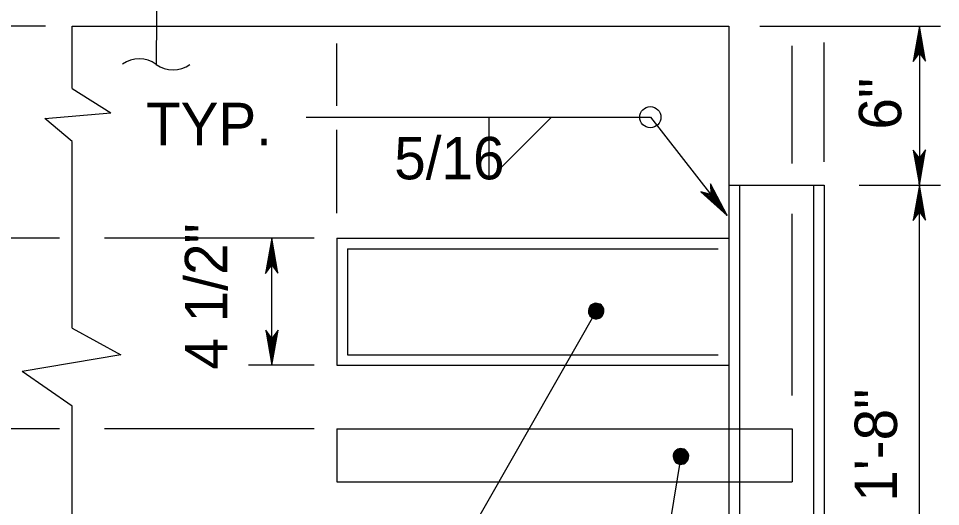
# Model space of a CAD drawing. Extents: x 499883 to 500983, y 499104 to 499764.
# Drawn here: x 500293.1 to 500380.1, y 499651.5 to 499697.5 of the extents above; entities that cross this region are included whole.
import ezdxf

# ---------------------------------------------------------------- set-up
doc = ezdxf.new("R2010")
doc.units = 0
doc.layers.add('24', color=7, linetype='Continuous')
doc.layers.add('5', color=7, linetype='Continuous')

msp = doc.modelspace()

# ---------------------------------------------------------------- linework, layer by layer
at = {"layer": '24'}
for points in [[(500347.639, 499669.947), (500304.956, 499595.144), (500297.036, 499595.144)], [(500355.634, 499656.248), (500348.094, 499610.467), (500342.218, 499610.467)]]:
    msp.add_lwpolyline(points, dxfattribs=at)
for centre, radius, start, end in [((500304.512, 499690.964), 2.768, 54.46959, 124.83479), ((500307.729, 499695.47), 2.768, 234.46959, 304.83479), ((500347.638, 499669.947), 0.738, 60.29128, 240.29128), ((500347.638, 499669.947), 0.714, 60.29128, 240.29128), ((500347.638, 499669.947), 0.689, 60.29128, 240.29128), ((500347.638, 499669.947), 0.664, 60.29128, 240.29128), ((500347.638, 499669.947), 0.64, 60.29128, 240.29128), ((500347.638, 499669.947), 0.615, 60.29128, 240.29128), ((500347.638, 499669.947), 0.591, 60.29128, 240.29128), ((500347.638, 499669.947), 0.566, 60.29128, 240.29128), ((500347.638, 499669.947), 0.541, 60.29128, 240.29128), ((500347.638, 499669.947), 0.517, 60.29128, 240.29128), ((500347.638, 499669.947), 0.492, 60.29128, 240.29128), ((500347.638, 499669.947), 0.468, 60.29128, 240.29128), ((500347.638, 499669.947), 0.443, 60.29128, 240.29128), ((500347.638, 499669.947), 0.418, 60.29128, 240.29128), ((500347.638, 499669.947), 0.394, 60.29128, 240.29128), ((500347.638, 499669.947), 0.369, 60.29128, 240.29128), ((500347.638, 499669.947), 0.738, 240.29128, 60.29128), ((500347.638, 499669.947), 0.714, 240.29128, 60.29128), ((500347.638, 499669.947), 0.344, 60.29128, 240.29128), ((500347.638, 499669.947), 0.689, 240.29128, 60.29128), ((500347.638, 499669.947), 0.664, 240.29128, 60.29128), ((500347.638, 499669.947), 0.32, 60.29128, 240.29128), ((500347.638, 499669.947), 0.64, 240.29128, 60.29128), ((500347.638, 499669.947), 0.615, 240.29128, 60.29128), ((500347.638, 499669.947), 0.295, 60.29128, 240.29128), ((500347.638, 499669.947), 0.591, 240.29128, 60.29128), ((500347.638, 499669.947), 0.566, 240.29128, 60.29128), ((500347.638, 499669.947), 0.541, 240.29128, 60.29128), ((500347.638, 499669.947), 0.517, 240.29128, 60.29128), ((500347.638, 499669.947), 0.492, 240.29128, 60.29128), ((500347.638, 499669.947), 0.468, 240.29128, 60.29128), ((500347.638, 499669.947), 0.443, 240.29128, 60.29128), ((500347.638, 499669.947), 0.418, 240.29128, 60.29128), ((500347.638, 499669.947), 0.394, 240.29128, 60.29128), ((500347.638, 499669.947), 0.369, 240.29128, 60.29128), ((500347.638, 499669.947), 0.344, 240.29128, 60.29128), ((500347.638, 499669.947), 0.271, 60.29128, 240.29128), ((500347.638, 499669.947), 0.246, 60.29128, 240.29128), ((500347.638, 499669.947), 0.221, 60.29128, 240.29128), ((500347.638, 499669.947), 0.197, 60.29128, 240.29128), ((500347.638, 499669.947), 0.172, 60.29128, 240.29128), ((500347.638, 499669.947), 0.32, 240.29128, 60.29128), ((500347.638, 499669.947), 0.148, 60.29128, 240.29128), ((500347.638, 499669.947), 0.295, 240.29128, 60.29128), ((500347.638, 499669.947), 0.271, 240.29128, 60.29128), ((500347.638, 499669.947), 0.123, 60.29128, 240.29128), ((500347.638, 499669.947), 0.246, 240.29128, 60.29128), ((500347.638, 499669.947), 0.221, 240.29128, 60.29128), ((500347.638, 499669.947), 0.0984, 60.29128, 240.29128), ((500347.638, 499669.947), 0.197, 240.29128, 60.29128), ((500347.638, 499669.947), 0.172, 240.29128, 60.29128), ((500347.638, 499669.947), 0.148, 240.29128, 60.29128), ((500347.638, 499669.947), 0.0738, 60.29128, 240.29128), ((500347.638, 499669.947), 0.123, 240.29128, 60.29128), ((500347.638, 499669.947), 0.0492, 60.29128, 240.29128), ((500347.638, 499669.947), 0.0984, 240.29128, 60.29128), ((500347.638, 499669.947), 0.0738, 240.29128, 60.29128), ((500347.638, 499669.947), 0.0492, 240.29128, 60.29128), ((500347.638, 499669.947), 0.0246, 60.29128, 240.29128), ((500347.638, 499669.947), 0.0246, 240.29128, 60.29128), ((500355.634, 499656.247), 0.738, 80.64766, 260.64766), ((500355.634, 499656.247), 0.714, 80.64766, 260.64766), ((500355.634, 499656.247), 0.689, 80.64766, 260.64766), ((500355.634, 499656.247), 0.664, 80.64766, 260.64766), ((500355.634, 499656.247), 0.64, 80.64766, 260.64766), ((500355.634, 499656.247), 0.615, 80.64766, 260.64766), ((500355.634, 499656.247), 0.591, 80.64766, 260.64766), ((500355.634, 499656.247), 0.566, 80.64766, 260.64766), ((500355.634, 499656.247), 0.541, 80.64766, 260.64766), ((500355.634, 499656.247), 0.517, 80.64766, 260.64766), ((500355.634, 499656.247), 0.492, 80.64766, 260.64766), ((500355.634, 499656.247), 0.468, 80.64766, 260.64766), ((500355.634, 499656.247), 0.443, 80.64766, 260.64766), ((500355.634, 499656.247), 0.418, 80.64766, 260.64766), ((500355.634, 499656.247), 0.394, 80.64766, 260.64766), ((500355.634, 499656.247), 0.369, 80.64766, 260.64766), ((500355.634, 499656.247), 0.344, 80.64766, 260.64766), ((500355.634, 499656.247), 0.32, 80.64766, 260.64766), ((500355.634, 499656.247), 0.295, 80.64766, 260.64766), ((500355.634, 499656.247), 0.271, 80.64766, 260.64766), ((500355.634, 499656.247), 0.246, 80.64766, 260.64766), ((500355.634, 499656.247), 0.221, 80.64766, 260.64766), ((500355.634, 499656.247), 0.197, 80.64766, 260.64766), ((500355.634, 499656.247), 0.172, 80.64766, 260.64766), ((500355.634, 499656.247), 0.148, 80.64766, 260.64766), ((500355.634, 499656.247), 0.123, 80.64766, 260.64766), ((500355.634, 499656.247), 0.738, 260.64766, 80.64766), ((500355.634, 499656.247), 0.714, 260.64766, 80.64766), ((500355.634, 499656.247), 0.689, 260.64766, 80.64766), ((500355.634, 499656.247), 0.664, 260.64766, 80.64766), ((500355.634, 499656.247), 0.64, 260.64766, 80.64766), ((500355.634, 499656.247), 0.615, 260.64766, 80.64766), ((500355.634, 499656.247), 0.0984, 80.64766, 260.64766), ((500355.634, 499656.247), 0.591, 260.64766, 80.64766), ((500355.634, 499656.247), 0.566, 260.64766, 80.64766), ((500355.634, 499656.247), 0.541, 260.64766, 80.64766), ((500355.634, 499656.247), 0.517, 260.64766, 80.64766), ((500355.634, 499656.247), 0.492, 260.64766, 80.64766), ((500355.634, 499656.247), 0.468, 260.64766, 80.64766), ((500355.634, 499656.247), 0.0738, 80.64766, 260.64766), ((500355.634, 499656.247), 0.443, 260.64766, 80.64766), ((500355.634, 499656.247), 0.418, 260.64766, 80.64766), ((500355.634, 499656.247), 0.394, 260.64766, 80.64766), ((500355.634, 499656.247), 0.369, 260.64766, 80.64766), ((500355.634, 499656.247), 0.344, 260.64766, 80.64766), ((500355.634, 499656.247), 0.32, 260.64766, 80.64766), ((500355.634, 499656.247), 0.295, 260.64766, 80.64766), ((500355.634, 499656.247), 0.271, 260.64766, 80.64766), ((500355.634, 499656.247), 0.246, 260.64766, 80.64766), ((500355.634, 499656.247), 0.221, 260.64766, 80.64766), ((500355.634, 499656.247), 0.197, 260.64766, 80.64766), ((500355.634, 499656.247), 0.172, 260.64766, 80.64766), ((500355.634, 499656.247), 0.148, 260.64766, 80.64766), ((500355.634, 499656.247), 0.123, 260.64766, 80.64766), ((500355.634, 499656.247), 0.0984, 260.64766, 80.64766), ((500355.634, 499656.247), 0.0738, 260.64766, 80.64766), ((500355.634, 499656.247), 0.0492, 80.64766, 260.64766), ((500355.634, 499656.247), 0.0246, 80.64766, 260.64766), ((500355.634, 499656.247), 0.0492, 260.64766, 80.64766), ((500355.634, 499656.247), 0.0246, 260.64766, 80.64766)]:
    msp.add_arc(centre, radius, start, end, dxfattribs=at)
at = {"layer": '5'}
for p, q in [((500295.678, 499696.814), (500284.277, 499696.814)), ((500298.192, 499696.814), (500360.145, 499696.814)), ((500298.192, 499690.928), (500298.192, 499696.814)), ((500360.145, 499696.814), (500360.145, 499681.826)), ((500363.071, 499696.814), (500380.13, 499696.814)), ((500378.131, 499696.814), (500378.131, 499681.826)), ((500323.174, 499689.306), (500323.174, 499695.177)), ((500366.141, 499683.862), (500366.141, 499694.949)), ((500369.139, 499684.02), (500369.139, 499695.265)), ((500298.192, 499690.928), (500301.847, 499688.646)), ((500295.625, 499688.117), (500301.847, 499688.646)), ((500298.192, 499685.939), (500295.625, 499688.117)), ((500320.265, 499688.235), (500352.747, 499688.235)), ((500343.42, 499688.235), (500337.529, 499682.344)), ((500337.529, 499682.344), (500337.529, 499688.235)), ((500352.747, 499688.235), (500360.005, 499678.955)), ((500323.174, 499679.192), (500323.174, 499687.045)), ((500298.192, 499668.328), (500298.192, 499685.939)), ((500360.145, 499681.826), (500369.139, 499681.826)), ((500360.145, 499681.826), (500360.145, 499630.865)), ((500361.144, 499681.826), (500361.144, 499630.865)), ((500368.139, 499681.826), (500368.139, 499630.865)), ((500369.139, 499681.826), (500369.139, 499616.875)), ((500372.436, 499681.826), (500380.13, 499681.826)), ((500378.131, 499630.865), (500378.131, 499681.826)), ((500366.141, 499662.004), (500366.141, 499679.11)), ((500296.993, 499676.83), (500284.277, 499676.83)), ((500321.027, 499676.83), (500301.229, 499676.83)), ((500317.03, 499664.839), (500317.03, 499676.83)), ((500323.174, 499676.83), (500360.145, 499676.83)), ((500323.174, 499676.83), (500323.174, 499664.839)), ((500324.173, 499675.831), (500359.146, 499675.831)), ((500324.173, 499675.831), (500324.173, 499665.838)), ((500298.192, 499668.328), (500302.773, 499665.813)), ((500302.773, 499665.813), (500293.463, 499664.268)), ((500324.173, 499665.838), (500359.146, 499665.838)), ((500298.192, 499660.998), (500293.463, 499664.268)), ((500321.027, 499664.839), (500314.819, 499664.839)), ((500323.174, 499664.839), (500360.145, 499664.839)), ((500298.192, 499636.713), (500298.192, 499660.998)), ((500296.993, 499658.843), (500284.277, 499658.843)), ((500321.027, 499658.843), (500301.229, 499658.843)), ((500323.174, 499658.843), (500366.141, 499658.843)), ((500323.174, 499658.843), (500323.174, 499653.847)), ((500366.141, 499658.843), (500366.141, 499653.847)), ((500323.174, 499653.847), (500366.141, 499653.847))]:
    msp.add_line(p, q, dxfattribs=at)
for points in [[(500301.41, 499711.376), (500306.231, 499711.376), (500306.121, 499693.217)], [(500378.131, 499696.814), (500377.544, 499693.491), (500378.131, 499694.284), (500378.71, 499693.508), (500378.131, 499696.814), (500378.138, 499696.593), (500377.588, 499693.584), (500378.139, 499694.347), (500378.664, 499693.642), (500378.148, 499696.475), (500378.131, 499696.364), (500377.674, 499693.785), (500378.139, 499694.364), (500378.59, 499693.769), (500378.131, 499696.313), (500378.148, 499696.203), (500377.741, 499693.949), (500378.131, 499694.387), (500378.537, 499693.94), (500378.148, 499695.882), (500378.148, 499695.694), (500377.825, 499694.116), (500378.122, 499694.423), (500378.453, 499694.093), (500378.131, 499695.661), (500378.121, 499695.483), (500377.918, 499694.297), (500378.149, 499694.525), (500378.376, 499694.278), (500378.131, 499695.32), (500378.115, 499695.153), (500377.979, 499694.44), (500378.139, 499694.558), (500378.316, 499694.363), (500378.131, 499695.066), (500378.021, 499694.601), (500378.148, 499694.668), (500378.275, 499694.464), (500378.149, 499694.949), (500378.072, 499694.644), (500378.173, 499694.772), (500378.233, 499694.625), (500378.139, 499694.771), (500378.122, 499694.695)], [(500378.131, 499681.826), (500378.719, 499685.15), (500378.131, 499684.356), (500377.553, 499685.132), (500378.131, 499681.826), (500378.125, 499682.047), (500378.676, 499685.057), (500378.124, 499684.293), (500377.599, 499684.998), (500378.115, 499682.166), (500378.131, 499682.276), (500378.59, 499684.855), (500378.125, 499684.276), (500377.674, 499684.872), (500378.132, 499682.327), (500378.115, 499682.438), (500378.522, 499684.691), (500378.132, 499684.253), (500377.726, 499684.701), (500378.115, 499682.758), (500378.115, 499682.946), (500378.438, 499684.524), (500378.141, 499684.217), (500377.81, 499684.548), (500378.131, 499682.979), (500378.141, 499683.157), (500378.345, 499684.344), (500378.115, 499684.116), (500377.887, 499684.363), (500378.131, 499683.32), (500378.148, 499683.488), (500378.285, 499684.2), (500378.124, 499684.083), (500377.947, 499684.277), (500378.132, 499683.574), (500378.242, 499684.039), (500378.115, 499683.972), (500377.988, 499684.176), (500378.115, 499683.691), (500378.191, 499683.996), (500378.09, 499683.869), (500378.031, 499684.015), (500378.124, 499683.869), (500378.141, 499683.946)], [(500360.005, 499678.955), (500358.42, 499681.935), (500358.446, 499680.947), (500357.513, 499681.203), (500360.005, 499678.955), (500359.864, 499679.125), (500358.443, 499681.834), (500358.479, 499680.894), (500357.631, 499681.125), (500359.783, 499679.212), (500359.727, 499679.309), (500358.5, 499681.623), (500358.49, 499680.88), (500357.768, 499681.071), (500359.696, 499679.349), (500359.615, 499679.426), (500358.547, 499681.452), (500358.51, 499680.866), (500357.915, 499680.969), (500359.417, 499679.679), (500359.302, 499679.827), (500358.584, 499681.269), (500358.539, 499680.844), (500358.075, 499680.9), (500359.294, 499679.863), (500359.193, 499680.009), (500358.622, 499681.069), (500358.581, 499680.748), (500358.249, 499680.802), (500359.084, 499680.131), (500358.995, 499680.274), (500358.663, 499680.919), (500358.609, 499680.728), (500358.349, 499680.771), (500358.928, 499680.332), (500358.729, 499680.766), (500358.67, 499680.635), (500358.444, 499680.717), (500358.842, 499680.413), (500358.715, 499680.701), (500358.714, 499680.538), (500358.577, 499680.617), (500358.741, 499680.56), (500358.706, 499680.63)], [(500378.131, 499681.826), (500377.544, 499678.502), (500378.131, 499679.296), (500378.71, 499678.519), (500378.131, 499681.826), (500378.138, 499681.605), (500377.588, 499678.595), (500378.139, 499679.358), (500378.664, 499678.653), (500378.148, 499681.486), (500378.131, 499681.375), (500377.674, 499678.797), (500378.139, 499679.375), (500378.59, 499678.78), (500378.131, 499681.325), (500378.148, 499681.214), (500377.741, 499678.96), (500378.131, 499679.398), (500378.537, 499678.951), (500378.148, 499680.893), (500378.148, 499680.706), (500377.825, 499679.127), (500378.122, 499679.435), (500378.453, 499679.104), (500378.131, 499680.672), (500378.121, 499680.495), (500377.918, 499679.308), (500378.149, 499679.536), (500378.376, 499679.289), (500378.131, 499680.332), (500378.115, 499680.164), (500377.979, 499679.452), (500378.139, 499679.569), (500378.316, 499679.375), (500378.131, 499680.077), (500378.021, 499679.613), (500378.148, 499679.68), (500378.275, 499679.476), (500378.149, 499679.96), (500378.072, 499679.656), (500378.173, 499679.783), (500378.233, 499679.637), (500378.139, 499679.782), (500378.122, 499679.706)], [(500317.03, 499676.83), (500316.442, 499673.506), (500317.03, 499674.3), (500317.608, 499673.523), (500317.03, 499676.83), (500317.036, 499676.609), (500316.486, 499673.599), (500317.037, 499674.362), (500317.563, 499673.657), (500317.046, 499676.49), (500317.03, 499676.379), (500316.572, 499673.801), (500317.037, 499674.379), (500317.488, 499673.784), (500317.03, 499676.329), (500317.046, 499676.218), (500316.64, 499673.964), (500317.03, 499674.402), (500317.435, 499673.955), (500317.047, 499675.897), (500317.046, 499675.709), (500316.724, 499674.131), (500317.02, 499674.438), (500317.351, 499674.108), (500317.03, 499675.676), (500317.019, 499675.499), (500316.816, 499674.312), (500317.047, 499674.54), (500317.274, 499674.293), (500317.03, 499675.335), (500317.013, 499675.168), (500316.877, 499674.455), (500317.037, 499674.573), (500317.214, 499674.378), (500317.029, 499675.081), (500316.92, 499674.617), (500317.046, 499674.684), (500317.174, 499674.48), (500317.047, 499674.964), (500316.97, 499674.659), (500317.071, 499674.787), (500317.131, 499674.64), (500317.037, 499674.786), (500317.02, 499674.71)], [(500317.03, 499664.839), (500317.618, 499668.163), (500317.03, 499667.369), (500316.452, 499668.146), (500317.03, 499664.839), (500317.024, 499665.06), (500317.574, 499668.069), (500317.023, 499667.307), (500316.497, 499668.011), (500317.014, 499665.179), (500317.03, 499665.29), (500317.488, 499667.868), (500317.023, 499667.289), (500316.572, 499667.884), (500317.03, 499665.34), (500317.014, 499665.45), (500317.42, 499667.705), (500317.03, 499667.266), (500316.625, 499667.713), (500317.013, 499665.771), (500317.013, 499665.959), (500317.336, 499667.537), (500317.039, 499667.23), (500316.709, 499667.561), (500317.03, 499665.992), (500317.04, 499666.17), (500317.243, 499667.356), (500317.013, 499667.128), (500316.785, 499667.376), (500317.03, 499666.333), (500317.047, 499666.5), (500317.183, 499667.213), (500317.023, 499667.096), (500316.845, 499667.29), (500317.03, 499666.587), (500317.141, 499667.052), (500317.013, 499666.985), (500316.886, 499667.189), (500317.013, 499666.704), (500317.09, 499667.009), (500316.989, 499666.881), (500316.929, 499667.028), (500317.023, 499666.882), (500317.039, 499666.959)]]:
    msp.add_lwpolyline(points, dxfattribs=at)
msp.add_circle((500352.747, 499688.235), 0.999, dxfattribs=at)

# ---------------------------------------------------------------- texts
for s, p in [('6"', (500376.425, 499687.063)), ('4 1/2"', (500312.824, 499664.431)), ('1\'-8"', (500376.024, 499651.978))]:
    msp.add_text(s, height=4, rotation=90, dxfattribs=at).set_placement(p)
for s, p in [('TYP.', (500305.158, 499685.595)), ('5/16', (500328.579, 499682.373))]:
    msp.add_text(s, height=4, dxfattribs=at).set_placement(p)

doc.saveas('drawing.dxf')
